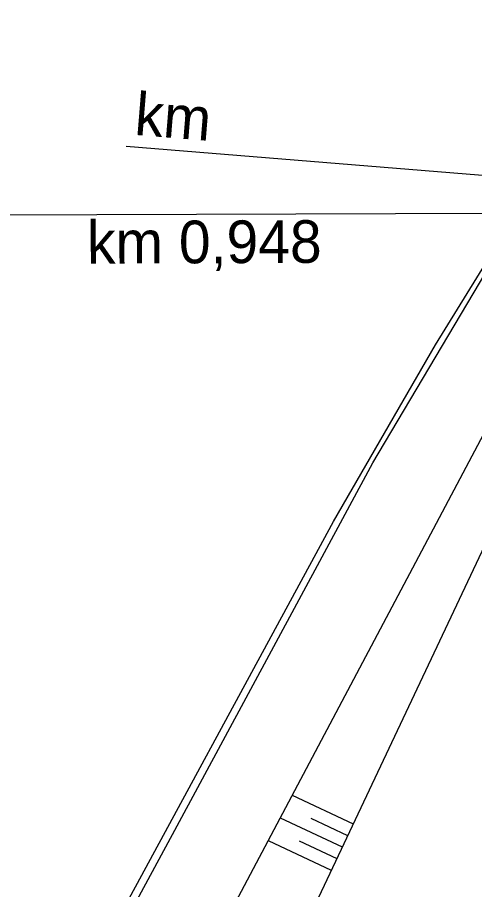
# Model space of a CAD drawing. Extents: x -598638 to -597933, y -1164002 to -1161904.
# Drawn here: x -598309.4 to -598282.7, y -1163148.3 to -1163097.2 of the extents above; entities that cross this region are included whole.
import ezdxf

# ---------------------------------------------------------------- set-up
doc = ezdxf.new("R2010")
doc.units = 0
for name, color, linetype in [('Vrstva 1', 7, 'Continuous'), ('Vrstva 26', 7, 'Continuous'), ('Vrstva 28', 7, 'Continuous'), ('Vrstva 48', 7, 'Continuous'), ('Vrstva 49', 7, 'Continuous'), ('Vrstva 6', 7, 'Continuous')]:
    doc.layers.add(name, color=color, linetype=linetype)

msp = doc.modelspace()

# ---------------------------------------------------------------- linework, layer by layer
at = {"layer": 'Vrstva 1'}
msp.add_line((-598328.722, -1163108.807), (-598252.219, -1163108.544), dxfattribs=at)
at = {"layer": 'Vrstva 26'}
msp.add_lwpolyline([(-598329.728, -1163196.743), (-598319.392, -1163178.856), (-598305.552, -1163153.711), (-598290.936, -1163126.707), (-598284.955, -1163116.365), (-598274.949, -1163100.139)], dxfattribs=at)
at = {"layer": 'Vrstva 28'}
msp.add_lwpolyline([(-598311.69, -1163165.97), (-598300.22, -1163144.81), (-598288.63, -1163123.27), (-598282.38, -1163112.74), (-598276.94, -1163103.58), (-598276.43, -1163102.81), (-598275.67, -1163101.85), (-598275.32, -1163101.07), (-598273.79, -1163098.83), (-598261.6, -1163097.17), (-598260.92, -1163098.05), (-598264.78, -1163103.58), (-598264.9, -1163104.07), (-598265.13, -1163109.86), (-598265.13, -1163112.72), (-598265.03, -1163116.78), (-598265.37, -1163120.79), (-598265.62, -1163131.18), (-598265.34, -1163148.04), (-598265.46, -1163176.63)], dxfattribs=at)
at = {"layer": 'Vrstva 48'}
for p, q in [((-598293.345, -1163142.745), (-598289.782, -1163144.427)), ((-598294.048, -1163144.072), (-598290.422, -1163145.784)), ((-598292.259, -1163144.088), (-598290.102, -1163145.105)), ((-598294.751, -1163145.399), (-598291.062, -1163147.14)), ((-598292.937, -1163145.426), (-598290.742, -1163146.462))]:
    msp.add_line(p, q, dxfattribs=at)
at = {"layer": 'Vrstva 49'}
for points in [[(-598263.212, -1163112.925), (-598274.704, -1163107.546), (-598303.252, -1163161.452), (-598319.987, -1163201.454), (-598331.61, -1163221.279), (-598337.803, -1163227.955), (-598369.667, -1163281.996), (-598397.721, -1163336.904), (-598402.66, -1163348.84), (-598400.565, -1163353.737), (-598397.481, -1163355.879), (-598399.949, -1163362.495), (-598406.763, -1163364.325), (-598409.804, -1163366.381), (-598423.526, -1163399.322), (-598428.665, -1163409.066), (-598433.221, -1163423.229), (-598435.507, -1163449.626)], [(-598271.914, -1163217.222), (-598269.776, -1163209.288), (-598269.073, -1163206.337), (-598265.809, -1163203.939), (-598262.679, -1163201.583), (-598261.749, -1163188.913), (-598261.649, -1163166.383), (-598262.017, -1163142.76), (-598263.36, -1163128.202), (-598263.105, -1163118.751), (-598268.545, -1163115.616), (-598275.334, -1163113.816), (-598312.096, -1163191.704), (-598312.746, -1163196.691)]]:
    msp.add_lwpolyline(points, dxfattribs=at)
at = {"layer": 'Vrstva 6'}
msp.add_line((-598303.072, -1163104.716), (-598246.44, -1163109.31), dxfattribs=at)

# ---------------------------------------------------------------- texts
at = {"layer": 'Vrstva 1'}
msp.add_text('km 0,948', height=2.5, rotation=0.1932, dxfattribs=at).set_placement((-598305.37, -1163111.598))
at = {"layer": 'Vrstva 6'}
msp.add_text('km ', height=2.5, rotation=355.3624, dxfattribs=at).set_placement((-598302.638, -1163104.048))

doc.saveas('drawing.dxf')
